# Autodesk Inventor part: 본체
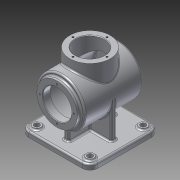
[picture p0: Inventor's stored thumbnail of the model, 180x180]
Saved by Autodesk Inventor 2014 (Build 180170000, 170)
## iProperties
Created: 2015-07
Part Number: 본체
Material: 알루미늄 6061
Document SubType Name: Modeling
Designer: basic
Density: 2.71 g/cm^3
Appearance: 알루미늄 - 평지
Mass: 1275.15 g
Surface Area: 1282.11 cm^2
Volume: 470.533 cm^3
Author: basic
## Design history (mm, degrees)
sketch "스케치1"
  geometry: L1 (-65, 65)-(65, 65); L2 (65, 65)-(65, -65); L3 (65, -65)-(-65, -65); L4 (-65, -65)-(-65, 65); 3 further points
  constraints: 8 end point, 2 midpoint, 2 parallel, 2 perpendicular, 1 horizontal, 1 horizontal alignment, 1 vertical alignment
  dimensions: "d0" = 130 distance of L1.start L1.end
extrude "돌출1" new body sketch "스케치1" distance "d1" = 10; taper "d2" = 0 deg
fillet "모깎기1" dims "d3" = 15
sketch "스케치2"
  geometry: C1 r 7.5 at (50, 50); C2 r 7.5 at (50, -50); C3 r 7.5 at (-50, -50); C4 r 7.5 at (-50, 50); A1 r 15 centre (-50, 50) between (-50, 65) and (-65, 50) reference; A2 r 15 centre (-50, -50) between (-65, -50) and (-50, -65) reference; A3 r 15 centre (50, -50) between (50, -65) and (65, -50) reference; A4 r 15 centre (50, 50) between (65, 50) and (50, 65) reference; 1 further point
  constraints: 4 centre point, 4 coincident, 3 equal radius
  dimensions: "d4" = 15 diameter of C1
extrude "돌출2" join sketch "스케치2" distance "d5" = 3; taper "d6" = 0 deg
sketch "스케치3"
  geometry: C1 r 7.5 at (0, 0) reference; C2 r 5 at (0, 0); 1 further point
  constraints: 1 centre point, 1 coincident
  dimensions: "d7" = 10 diameter of C2
extrude "돌출3" cut sketch "스케치3" stored distance "d8" = 3; taper "d9" = 0 deg
sketch "스케치4"
  geometry: C1 r 7.5 at (0, 0) reference; C2 r 5 at (0, 0); 1 further point
  constraints: 1 centre point, 1 coincident
  dimensions: "d10" = 10 diameter of C2
extrude "돌출4" cut sketch "스케치4" stored distance "d11" = 3; taper "d12" = 0 deg
sketch "스케치5"
  geometry: C1 r 7.5 at (0, 0) reference; C2 r 5 at (0, 0); 1 further point
  constraints: 1 centre point, 1 coincident
  dimensions: "d13" = 10 diameter of C2
extrude "돌출5" cut sketch "스케치5" stored distance "d14" = 3; taper "d15" = 0 deg
sketch "스케치6"
  geometry: C1 r 7.5 at (0, 0) reference; C2 r 5 at (0, 0); 1 further point
  constraints: 1 centre point, 1 coincident
  dimensions: "d16" = 10 diameter of C2
extrude "돌출6" cut sketch "스케치6" stored distance "d17" = 3; taper "d18" = 0 deg
fillet "모깎기2" dims "d19" = 3
fillet "모깎기3" dims "d20" = 3
sketch "스케치7"
  geometry: L1 (-62, 10)-(62, 10) reference; L2 (65, 7)-(65, 0) reference; L3 (65, 0)-(-65, 0) reference; L4 (-65, 0)-(-65, 7) reference; C1 r 45 at (0, 78); A1 r 3 centre (-62, 7) between (-62, 10) and (-65, 7) reference; A2 r 3 centre (62, 7) between (65, 7) and (62, 10) reference; 2 further points
  constraints: 1 centre point, 1 midpoint, 1 vertical alignment
  dimensions: "d21" = 90 diameter of C1; "d22" = 78 distance from line of C1.centre L3
extrude "돌출7" join sketch "스케치7" stored distance "d23" = 110; taper "d24" = 0 deg
sketch "스케치8"
  geometry: L1 (65, 7)-(65, 0) reference; L2 (65, 0)-(-65, 0) reference; L3 (-65, 0)-(-65, 7) reference; L4 (-62, 10)-(62, 10) reference; L5 (-55, 33)-(-55, 123) reference; L6 (-55, 123)-(55, 123) reference; L7 (55, 123)-(55, 33) reference; L8 (55, 33)-(-55, 33) reference; L9 (55, 78)-(-62, 78); L10 (-62, 78)-(-62, 116); L11 (-62, 116)-(-55, 116); L12 (-55, 116)-(-55, 78); L13 (-55, 78)-(-62, 78); A1 r 3 centre (62, 7) between (65, 7) and (62, 10) reference; A2 r 3 centre (-62, 7) between (-62, 10) and (-65, 7) reference; 1 further point
  constraints: 10 end point, 2 midpoint, 2 perpendicular, 2 point on line, 1 collinear, 1 parallel
  dimensions: "d25" = 76 diameter of L11 L9; "d26" = 7 distance of L10.end L11.end
revolve "회전1" sketch "스케치8" stored, may be unused: angle "d27" = 90 deg
sketch "스케치9"
  geometry: L1 (-62, 40)-(-62, 116) reference; L2 (-62, 116)-(-55, 116) reference; L3 (-55, 116)-(-55, 123) reference; L4 (-55, 123)-(55, 123) reference; L5 (55, 123)-(55, 33) reference; L6 (55, 33)-(-55, 33) reference; L7 (-55, 33)-(-55, 40) reference; L8 (-55, 40)-(-62, 40) reference; L9 (65, 7)-(65, 0) reference; L10 (65, 0)-(-65, 0) reference; L11 (-65, 0)-(-65, 7) reference; L12 (-62, 10)-(62, 10) reference; L13 (55, 78)-(-62, 78); L14 (48, 78)-(48, 118); L15 (-48, 118)-(-48, 105); L16 (-48, 105)-(-62, 105); L17 (48, 118)-(-48, 118); A1 r 3 centre (62, 7) between (65, 7) and (62, 10) reference; A2 r 3 centre (-62, 7) between (-62, 10) and (-65, 7) reference; 1 further point
  constraints: 10 end point, 2 midpoint, 2 point on line, 1 horizontal, 1 parallel, 1 perpendicular, 1 vertical
  dimensions: "d28" = 7 distance between parallel lines of L5 L14; "d31" = 80 diameter of L17 L13; "d32" = 96 distance of L14.end L15.start; "d33" = 54 diameter of L16 L13
revolve "회전2" sketch "스케치9" stored, may be unused: angle "d34" = 90 deg
node "작업 평면1"
chamfer "모따기1" distance "d54" = 1; stored, may be unused: second distance "d55" = 2, angle "d56" = 45 deg
fillet "모깎기4" dims "d57" = 3
fillet "모깎기6" dims "d59" = 3
sketch "스케치13" dims "d60" = 64
  geometry: L1 (0, 0)-(0, 32); C1 r 28 at (0, 0) reference; C2 r 2 at (0, 32); 1 further point
  constraints: 2 coincident, 2 end point, 1 centre point, 1 vertical, 1 vertical alignment, 2 other
  dimensions: "d61" = 4 diameter of C2
hole "구멍2" sketch "스케치13" at (0, 32) diameter "d62" = 3.459; stored, may be unused: countersink angle "d66" = 90 deg, drill point angle "d68" = 118 deg; dims "d63" = 8, "d64" = 4, "d65" = 2, "d67" = 10
sketch "스케치16"
  geometry: L1 (-5, 45)-(5, 45); L2 (5, 45)-(5, -45); L3 (5, -45)-(-5, -45); L4 (-5, -45)-(-5, 45); 3 further points
  constraints: 8 end point, 2 midpoint, 2 parallel, 1 horizontal, 1 horizontal alignment, 1 perpendicular, 1 vertical alignment
  dimensions: "d81" = 10 distance of L1.start L1.end; "d82" = 90 distance of L1.end L2.end
extrude "돌출11" join sketch "스케치16" stored distance "d83" = 110; taper "d84" = 0 deg
sketch "스케치17"
  geometry: L1 (5, 33.279)-(5, 10) reference; L2 (5, 10)-(62, 10) reference; L3 (65, 7)-(65, 0) reference; L4 (65, 0)-(-65, 0) reference; L5 (-65, 0)-(-65, 7) reference; L6 (-62, 10)-(-5, 10) reference; L7 (-5, 10)-(-5, 33.279) reference; L8 (45, 78)-(45, 10); L9 (-45, 78)-(-45, 10); C1 r 40 at (0, 78) reference; A1 r 3 centre (62, 7) between (65, 7) and (62, 10) reference; A2 r 3 centre (-62, 7) between (-62, 10) and (-65, 7) reference; A3 r 45 centre (0, 78) between (5, 33.279) and (-5, 33.279) reference; 1 further point
  constraints: 4 end point, 2 perpendicular, 2 point on line
feature "리브1" sketch "스케치17" dims "d85" = 1, "d86" = 10, "d87" = 0, "d88" = 0, "d89" = 1, "d90" = 1
fillet "모깎기9" dims "d91" = 3
sketch "스케치18"
  geometry: C1 r 42 at (0, 0) reference; 2 further points
  constraints: 2 coincident, 1 other
feature "엠보싱1" sketch "스케치18" dims "d92" = 0.5, "d93" = 0
node "작업 평면2"
sketch "스케치19"
  geometry: C1 r 38 at (0, 0); 1 further point
  constraints: 1 centre point, 1 coincident
  dimensions: "d95" = 76 diameter of C1
extrude "돌출12" join sketch "스케치19" stored distance "d96" = 110; taper "d97" = 0 deg
fillet "모깎기10" dims "d98" = 3
sketch "스케치20"
  geometry: C1 r 38 at (0, 0) reference; C2 r 27 at (0, 0)
  constraints: 1 centre point, 1 coincident
  dimensions: "d99" = 54 diameter of C2
extrude "돌출13" cut sketch "스케치20" stored distance "d100" = 110; taper "d101" = 0 deg
chamfer "모따기2" distance "d102" = 1; stored, may be unused: second distance "d103" = 2, angle "d104" = 45 deg
sketch "스케치21" dims "d105" = 64
  geometry: L1 (0, 0)-(0, 32); C1 r 28 at (0, 0) reference; C2 r 2 at (0, 32)
  constraints: 2 coincident, 2 end point, 1 centre point, 1 vertical, 1 vertical alignment, 2 other
  dimensions: "d106" = 4 diameter of C2
hole "구멍3" sketch "스케치21" at (0, 32) diameter "d107" = 3.459; stored, may be unused: countersink angle "d111" = 90 deg, drill point angle "d113" = 118 deg; dims "d108" = 8, "d109" = 4, "d110" = 2, "d112" = 10
fillet "모깎기11" dims "d117" = 3
fillet "모깎기12" dims "d118" = 3
fillet "모깎기13" dims "d119" = 3
node "솔리드1"
pattern_circular "원형 패턴2" dims angle "d70" = 360 deg
mirror "대칭1"
pattern_circular "원형 패턴3" dims angle "d115" = 360 deg
node "절단 모서리 투영1"
node "절단 모서리 투영2"
node "절단 모서리 투영3"
node "절단 모서리 투영5"
